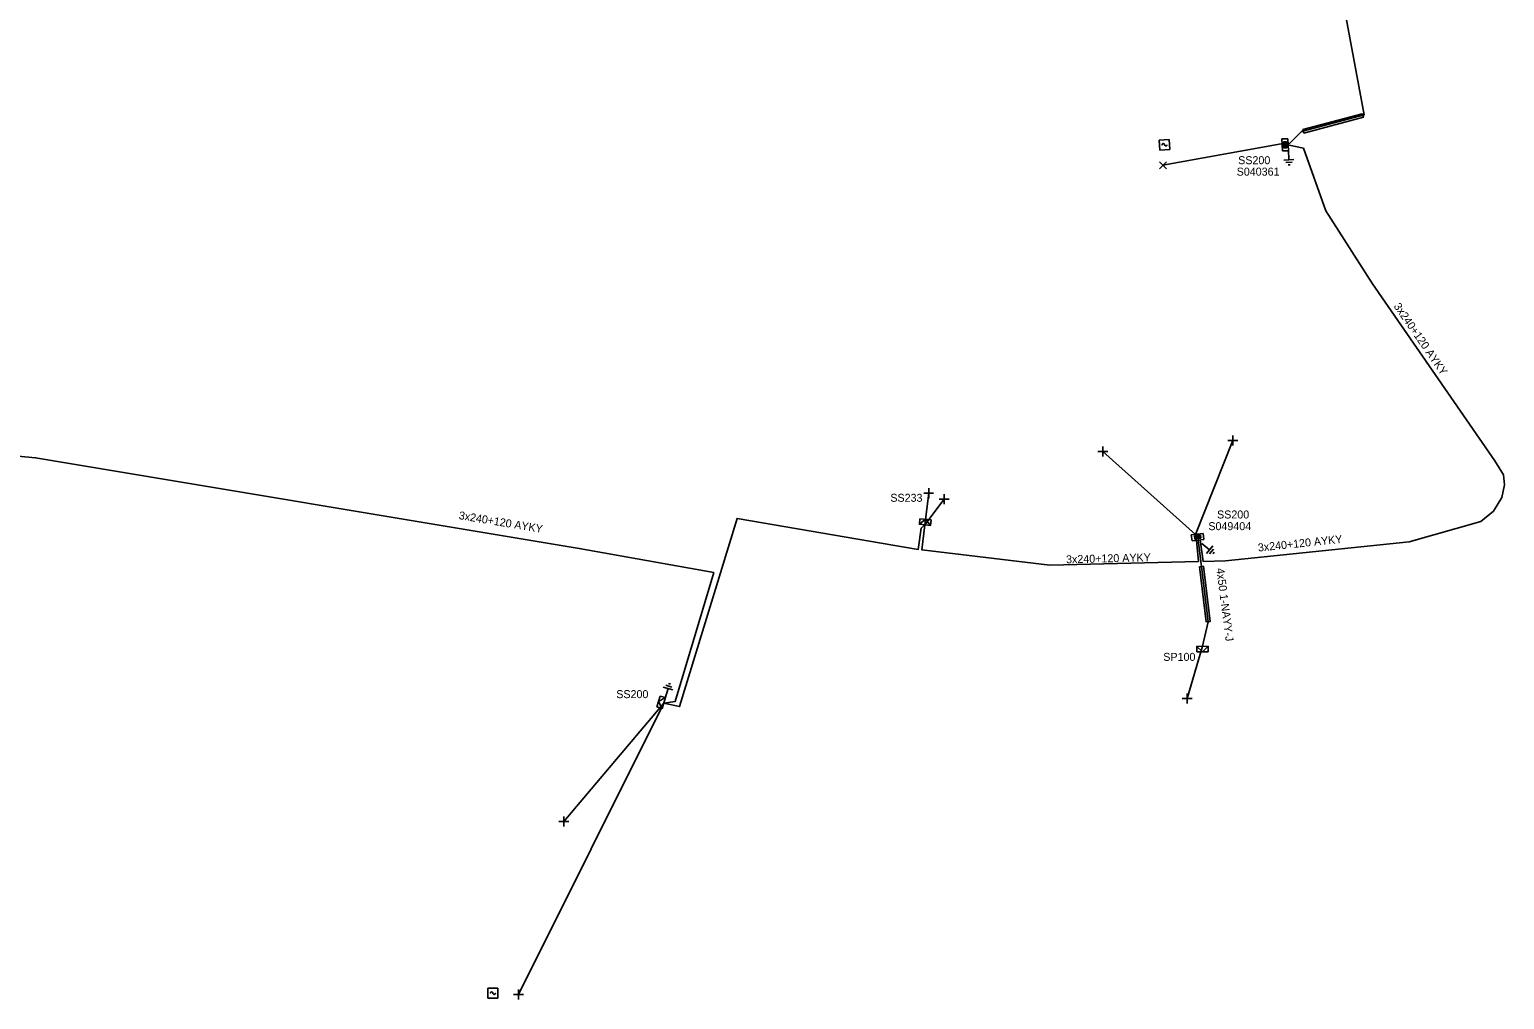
# Model space of a CAD drawing. Extents: x -748492 to -735633, y -1146251 to -1139940.
# Drawn here: x -740895.8 to -740711.5, y -1144778.9 to -1144657.6 of the extents above; entities that cross this region are included whole.
import ezdxf

# ---------------------------------------------------------------- set-up
doc = ezdxf.new("R2010")
doc.units = 0
for name, color, linetype in [('Vrstva 1', 7, 'Continuous'), ('Vrstva 14', 7, 'Continuous'), ('Vrstva 15', 7, 'Continuous'), ('Vrstva 20', 7, 'Continuous'), ('Vrstva 28', 7, 'Continuous'), ('Vrstva 29', 7, 'Continuous'), ('Vrstva 30', 7, 'Continuous'), ('Vrstva 31', 7, 'Continuous'), ('Vrstva 33', 7, 'Continuous'), ('Vrstva 34', 7, 'Continuous'), ('Vrstva 5', 7, 'Continuous'), ('Vrstva 59', 7, 'Continuous'), ('Vrstva 6', 7, 'Continuous'), ('Vrstva 8', 7, 'Continuous'), ('Vrstva 9', 7, 'Continuous')]:
    doc.layers.add(name, color=color, linetype=linetype)

# ---------------------------------------------------------------- blocks, each defined once
blk = doc.blocks.new('NN800')
at = {"layer": 'Vrstva 1'}
for points in [[(-0.44, 0.44), (0.44, -0.44)], [(-0.44, -0.44), (0.44, 0.44)]]:
    blk.add_lwpolyline(points, dxfattribs=at)
blk = doc.blocks.new('NN620')
at = {"layer": 'Vrstva 8'}
for points in [[(0.75, 0), (-0.75, 0)], [(-0.75, 0), (-0.75, -0.75)], [(0.75, -0.75), (0.75, 0)], [(-0.75, -0.75), (0.75, -0.75)], [(0.37, -0.18), (-0.38, -0.18)], [(-0.38, -0.18), (-0.38, -0.56)], [(-0.38, -0.56), (0.37, -0.56)], [(0.32, -0.23), (-0.33, -0.23)], [(-0.33, -0.23), (-0.33, -0.51)], [(-0.33, -0.51), (0.32, -0.51)], [(0.27, -0.27), (-0.28, -0.27)], [(-0.28, -0.27), (-0.28, -0.46)], [(-0.28, -0.46), (0.27, -0.46)], [(0.23, -0.32), (-0.23, -0.32)], [(-0.23, -0.32), (-0.23, -0.42)], [(-0.23, -0.42), (0.23, -0.42)], [(-0.19, -0.37), (0.19, -0.37)], [(0.23, -0.42), (0.23, -0.32)], [(0.27, -0.46), (0.27, -0.27)], [(0.32, -0.51), (0.32, -0.23)], [(0.37, -0.56), (0.37, -0.18)]]:
    blk.add_lwpolyline(points, dxfattribs=at)
blk = doc.blocks.new('NN630')
at = {"layer": 'Vrstva 9'}
for points in [[(0, -0.7), (-0.7, 0)], [(-0.7, -0.7), (-0.7, 0), (0.7, 0), (0.7, -0.7)], [(-0.7, -0.7), (0.7, -0.7)], [(0, -0.7), (0.7, 0)]]:
    blk.add_lwpolyline(points, dxfattribs=at)
blk = doc.blocks.new('NN810')
at = {"layer": 'Vrstva 14'}
for points in [[(0, -0.64), (0, -1.89)], [(0.63, -1.89), (-0.62, -1.89)], [(0.39, -2.2), (-0.4, -2.2)], [(0, -2.52), (-0.12, -2.52)], [(0.14, -2.52), (0, -2.52)]]:
    blk.add_lwpolyline(points, dxfattribs=at)
blk = doc.blocks.new('NN740')
at = {"layer": 'Vrstva 1'}
for points in [[(0.62, 0.62), (-0.63, 0.62)], [(-0.63, 0.62), (-0.63, -0.63)], [(0, 0), (0, 0.01), (0, 0.03), (-0.01, 0.05), (-0.01, 0.06), (-0.02, 0.08), (-0.03, 0.09), (-0.04, 0.1), (-0.05, 0.11), (-0.06, 0.12), (-0.08, 0.13), (-0.09, 0.14), (-0.11, 0.14), (-0.12, 0.15), (-0.14, 0.15), (-0.15, 0.15), (-0.17, 0.15), (-0.18, 0.15), (-0.2, 0.15), (-0.21, 0.14), (-0.23, 0.13), (-0.24, 0.12), (-0.26, 0.11), (-0.27, 0.1), (-0.28, 0.09), (-0.29, 0.08), (-0.29, 0.06), (-0.3, 0.05), (-0.3, 0.03), (-0.31, 0.02), (-0.31, 0), (-0.31, 0)], [(0.62, -0.63), (0.62, 0.62)], [(-0.63, -0.63), (0.62, -0.63)], [(0, 0), (0, -0.02), (0, -0.03), (0.01, -0.05), (0.01, -0.06), (0.02, -0.08), (0.03, -0.09), (0.04, -0.1), (0.05, -0.11), (0.06, -0.12), (0.07, -0.13), (0.09, -0.14), (0.1, -0.15), (0.12, -0.15), (0.13, -0.15), (0.15, -0.15), (0.16, -0.15), (0.18, -0.15), (0.19, -0.15), (0.21, -0.14), (0.22, -0.14), (0.24, -0.13), (0.25, -0.12), (0.26, -0.11), (0.27, -0.09), (0.28, -0.08), (0.29, -0.07), (0.29, -0.05), (0.3, -0.04), (0.3, -0.02), (0.3, -0.01), (0.3, -0.01)]]:
    blk.add_lwpolyline(points, dxfattribs=at)

msp = doc.modelspace()

# ---------------------------------------------------------------- linework, layer by layer
at = {"layer": 'Vrstva 20'}
for points in [[(-740736.57, -1144670.56), (-740736.69, -1144670.12), (-740729.26, -1144668.14), (-740729.13, -1144668.57)], [(-740749.61, -1144724.78), (-740749.11, -1144724.72), (-740748.26, -1144731.61), (-740748.76, -1144731.67)]]:
    msp.add_lwpolyline(points, close=True, dxfattribs=at)
at = {"layer": 'Vrstva 5'}
for points in [[(-740738.41, -1144671.9), (-740736.84, -1144670.37), (-740729.03, -1144668.28), (-740732.13, -1144651.44), (-740731.29, -1144651.27), (-740732.15, -1144651.11), (-740732.45, -1144646.86), (-740732.59, -1144637.24), (-740732.35, -1144615.73), (-740730.31, -1144609.26), (-740730.35, -1144600.12), (-740730.44, -1144599.02)], [(-740749.53, -1144721.4), (-740749.16, -1144724.11), (-740746.36, -1144724.04), (-740723.41, -1144721.65), (-740714.44, -1144719.13), (-740712.87, -1144717.84), (-740711.81, -1144716.13), (-740711.49, -1144714.52), (-740711.63, -1144713.28), (-740712.69, -1144711.55), (-740727.98, -1144689.39), (-740733.8, -1144680.29), (-740736.62, -1144672.45), (-740738.38, -1144672.07)], [(-741010.91, -1144701.06), (-740952.28, -1144714.27), (-740922.8, -1144708.54), (-740895.05, -1144711.14), (-740827.12, -1144722.49), (-740810.3, -1144725.5), (-740815.13, -1144741.62), (-740816.55, -1144741.81), (-740814.57, -1144742.25), (-740807.39, -1144718.73), (-740784.75, -1144722.6), (-740784.39, -1144719.96), (-740783.92, -1144719.54), (-740784.29, -1144722.66), (-740768.31, -1144724.56), (-740749.74, -1144724.11), (-740749.99, -1144721.48)], [(-740749.24, -1144734.72), (-740748.51, -1144731.64), (-740749.36, -1144724.75), (-740749.79, -1144721.44)]]:
    msp.add_lwpolyline(points, dxfattribs=at)
at = {"layer": 'Vrstva 59'}
for points in [[(-740739.39, -1144671.9), (-740754.18, -1144674.58)], [(-740750.11, -1144720.74), (-740745.44, -1144709)], [(-740750.11, -1144720.74), (-740761.69, -1144710.38)], [(-740783.92, -1144719.54), (-740783.45, -1144715.57)], [(-740783.92, -1144719.54), (-740781.53, -1144716.33)], [(-740749.24, -1144734.72), (-740751.14, -1144741.24)], [(-740816.55, -1144741.81), (-740834.69, -1144778.25)], [(-740816.55, -1144741.81), (-740829.06, -1144756.63)]]:
    msp.add_lwpolyline(points, dxfattribs=at)

# ---------------------------------------------------------------- block references
at = {"layer": 'Vrstva 15'}
for p, rotation in [((-740738.52, -1144672.01), 2.5335971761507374), ((-740749.79, -1144721.44), 49.84747212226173), ((-740816.55, -1144741.81), 163.39641941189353)]:
    msp.add_blockref('NN810', p, dxfattribs=dict(at, rotation=rotation))
at = {"layer": 'Vrstva 28'}
for p, rotation in [((-740738.52, -1144672.01), -87.46640276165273), ((-740749.79, -1144721.44), -173.0318694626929)]:
    msp.add_blockref('NN620', p, dxfattribs=dict(at, rotation=rotation))
at = {"layer": 'Vrstva 31'}
for p, rotation in [((-740783.92, -1144719.54), 173.27059733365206), ((-740749.24, -1144734.72), 0.8335861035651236), ((-740816.55, -1144741.81), -106.60358056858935)]:
    msp.add_blockref('NN630', p, dxfattribs=dict(at, rotation=rotation))
at = {"layer": 'Vrstva 34'}
for name, p, rotation in [('NN740', (-740753.97, -1144672.02), 2.5335971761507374), ('NN800', (-740761.69, -1144710.38), 44.99999995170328), ('NN800', (-740745.44, -1144709), 44.99999995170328), ('NN800', (-740783.45, -1144715.57), 45), ('NN800', (-740781.53, -1144716.33), 45), ('NN800', (-740751.14, -1144741.24), 45), ('NN800', (-740829.06, -1144756.63), 45), ('NN800', (-740834.69, -1144778.25), 44.99999995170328)]:
    msp.add_blockref(name, p, dxfattribs=dict(at, rotation=rotation))
for name, p in [('NN800', (-740754.18, -1144674.58)), ('NN740', (-740837.9, -1144778.08))]:
    msp.add_blockref(name, p, dxfattribs=at)

# ---------------------------------------------------------------- texts
at = {"layer": 'Vrstva 29'}
for s, p in [('S040361', (-740744.96, -1144675.88)), ('S049404', (-740748.5, -1144720.2))]:
    msp.add_text(s, height=1, dxfattribs=at).set_placement(p)
at = {"layer": 'Vrstva 30'}
for p in [(-740744.77, -1144674.45), (-740747.41, -1144718.74)]:
    msp.add_text('SS200', height=1, dxfattribs=at).set_placement(p)
at = {"layer": 'Vrstva 33'}
for s, rotation, p in [('SS233', 359.929, (-740788.24, -1144716.65)), ('SS200', 0.009, (-740822.49, -1144741.2))]:
    msp.add_text(s, height=1, rotation=rotation, dxfattribs=at).set_placement(p)
msp.add_text('SP100', height=1, dxfattribs=at).set_placement((-740754.13, -1144736.54))
at = {"layer": 'Vrstva 6'}
for s, rotation, p in [('3x240+120 AYKY', 304.602, (-740725.39, -1144692.21)), ('3x240+120 AYKY', 350.52, (-740842.22, -1144718.81)), ('3x240+120 AYKY', 5.95, (-740742.25, -1144722.88)), ('3x240+120 AYKY', 1.388, (-740766.27, -1144724.35)), ('4x50 1-NAYY-J', 277.402, (-740747.51, -1144725.01))]:
    msp.add_text(s, height=1, rotation=rotation, dxfattribs=at).set_placement(p)

doc.saveas('drawing.dxf')
